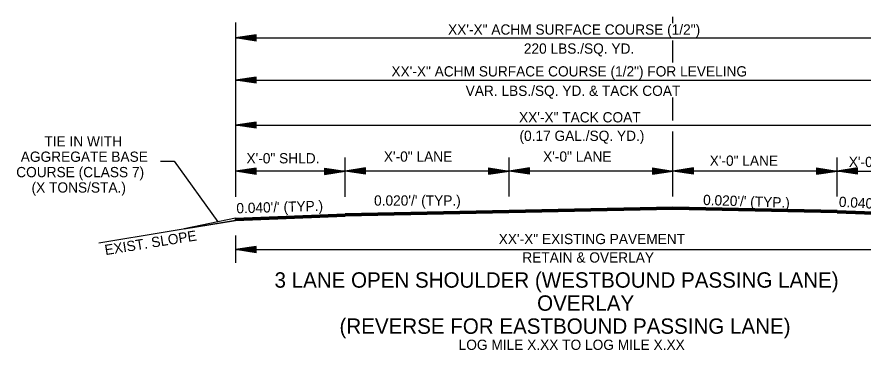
# Model space of a CAD drawing. Extents: x 544199 to 1930787, y -1968972 to 596640.
# Drawn here: x 551476 to 552096, y -1960786 to -1960542 of the extents above; entities that cross this region are included whole.
import ezdxf

# ---------------------------------------------------------------- set-up
doc = ezdxf.new("R2010")
doc.units = 0
doc.layers.add('R_Draft', color=7, linetype='Continuous')

msp = doc.modelspace()

# ---------------------------------------------------------------- linework, layer by layer
at = {"layer": 'R_Draft'}
for p, q in [((551636.39, -1960546.59), (551636.39, -1960674.01)), ((551956.58, -1960547.07), (551956.58, -1960542.46)), ((551651.39, -1960555.6), (551636.39, -1960557.85)), ((551636.39, -1960557.85), (552156.84, -1960557.85)), ((551651.39, -1960560.1), (551636.39, -1960557.85)), ((551651.39, -1960555.97), (551638.89, -1960557.85)), ((551651.39, -1960559.72), (551638.89, -1960557.85)), ((551651.39, -1960556.36), (551641.47, -1960557.85)), ((551651.39, -1960559.34), (551641.47, -1960557.85)), ((551651.39, -1960556.73), (551643.97, -1960557.85)), ((551651.39, -1960558.97), (551643.97, -1960557.85)), ((551651.39, -1960557.11), (551646.51, -1960557.85)), ((551651.39, -1960558.58), (551646.51, -1960557.85)), ((551651.39, -1960557.5), (551649.02, -1960557.85)), ((551651.39, -1960558.2), (551649.02, -1960557.85)), ((551651.39, -1960560.1), (551651.39, -1960555.6)), ((551956.58, -1960575.74), (551956.58, -1960559.67)), ((551651.39, -1960586.47), (551636.39, -1960588.72)), ((551636.39, -1960588.72), (552156.84, -1960588.72)), ((551651.39, -1960590.97), (551636.39, -1960588.72)), ((551651.39, -1960586.84), (551638.89, -1960588.72)), ((551651.39, -1960590.59), (551638.89, -1960588.72)), ((551651.39, -1960587.23), (551641.47, -1960588.72)), ((551651.39, -1960590.21), (551641.47, -1960588.72)), ((551651.39, -1960587.6), (551643.97, -1960588.72)), ((551651.39, -1960589.84), (551643.97, -1960588.72)), ((551651.39, -1960587.98), (551646.51, -1960588.72)), ((551651.39, -1960589.45), (551646.51, -1960588.72)), ((551651.39, -1960588.37), (551649.02, -1960588.72)), ((551651.39, -1960589.07), (551649.02, -1960588.72)), ((551651.39, -1960590.97), (551651.39, -1960586.47)), ((551956.58, -1960618.29), (551956.58, -1960601.42)), ((551651.39, -1960619.4), (551636.39, -1960621.65)), ((551651.39, -1960619.77), (551638.89, -1960621.65)), ((551651.39, -1960620.16), (551641.47, -1960621.65)), ((551651.39, -1960620.53), (551643.97, -1960621.65)), ((551651.39, -1960620.91), (551646.51, -1960621.65)), ((551651.39, -1960621.3), (551649.02, -1960621.65)), ((551651.39, -1960623.9), (551651.39, -1960619.4)), ((551636.39, -1960621.65), (552156.84, -1960621.65)), ((551651.39, -1960623.9), (551636.39, -1960621.65)), ((551651.39, -1960623.52), (551638.89, -1960621.65)), ((551651.39, -1960623.14), (551641.47, -1960621.65)), ((551651.39, -1960622.77), (551643.97, -1960621.65)), ((551651.39, -1960622.38), (551646.51, -1960621.65)), ((551651.39, -1960622), (551649.02, -1960621.65)), ((551956.58, -1960673.84), (551956.58, -1960626.29)), ((551716.65, -1960673.84), (551716.65, -1960645.29)), ((551716.65, -1960674.01), (551716.65, -1960645.29)), ((551836.65, -1960673.84), (551836.65, -1960645.29)), ((552076.84, -1960673.84), (552076.84, -1960645.29)), ((551651.39, -1960653.11), (551636.39, -1960655.36)), ((551716.65, -1960655.36), (551636.39, -1960655.36)), ((551651.39, -1960657.61), (551636.39, -1960655.36)), ((551651.39, -1960653.48), (551638.89, -1960655.36)), ((551651.39, -1960657.23), (551638.89, -1960655.36)), ((551651.39, -1960653.86), (551641.47, -1960655.36)), ((551651.39, -1960656.85), (551641.47, -1960655.36)), ((551651.39, -1960654.24), (551643.97, -1960655.36)), ((551651.39, -1960656.47), (551643.97, -1960655.36)), ((551651.39, -1960654.62), (551646.51, -1960655.36)), ((551651.39, -1960656.08), (551646.51, -1960655.36)), ((551651.39, -1960655), (551649.02, -1960655.36)), ((551651.39, -1960655.71), (551649.02, -1960655.36)), ((551651.39, -1960657.61), (551651.39, -1960653.11)), ((551701.65, -1960653.11), (551716.65, -1960655.36)), ((551701.65, -1960653.11), (551701.65, -1960657.61)), ((551701.65, -1960653.48), (551714.14, -1960655.36)), ((551701.65, -1960653.86), (551711.56, -1960655.36)), ((551701.65, -1960654.24), (551709.07, -1960655.36)), ((551701.65, -1960654.63), (551706.52, -1960655.36)), ((551701.65, -1960655), (551704.02, -1960655.36)), ((551701.65, -1960657.61), (551716.65, -1960655.36)), ((551701.65, -1960656.09), (551706.52, -1960655.36)), ((551701.65, -1960656.85), (551711.56, -1960655.36)), ((551701.65, -1960657.23), (551714.14, -1960655.36)), ((551701.65, -1960656.47), (551709.07, -1960655.36)), ((551701.65, -1960655.71), (551704.02, -1960655.36)), ((551731.65, -1960652.94), (551716.65, -1960655.19)), ((551836.65, -1960655.19), (551716.65, -1960655.19)), ((551731.65, -1960657.44), (551716.65, -1960655.19)), ((551731.65, -1960653.31), (551719.15, -1960655.19)), ((551731.65, -1960657.06), (551719.15, -1960655.19)), ((551731.65, -1960653.69), (551721.73, -1960655.19)), ((551731.65, -1960656.68), (551721.73, -1960655.19)), ((551731.65, -1960654.07), (551724.23, -1960655.19)), ((551731.65, -1960656.3), (551724.23, -1960655.19)), ((551731.65, -1960654.45), (551726.77, -1960655.19)), ((551731.65, -1960655.91), (551726.77, -1960655.19)), ((551731.65, -1960654.83), (551729.28, -1960655.19)), ((551731.65, -1960655.54), (551729.28, -1960655.19)), ((551731.65, -1960657.44), (551731.65, -1960652.94)), ((551821.65, -1960652.94), (551836.65, -1960655.19)), ((551821.65, -1960652.94), (551821.65, -1960657.44)), ((551821.65, -1960653.31), (551834.14, -1960655.19)), ((551821.65, -1960653.69), (551831.56, -1960655.19)), ((551821.65, -1960654.07), (551829.07, -1960655.19)), ((551821.65, -1960654.46), (551826.52, -1960655.19)), ((551821.65, -1960654.83), (551824.02, -1960655.19)), ((551821.65, -1960657.44), (551836.65, -1960655.19)), ((551821.65, -1960655.92), (551826.52, -1960655.19)), ((551821.65, -1960656.68), (551831.56, -1960655.19)), ((551821.65, -1960657.06), (551834.14, -1960655.19)), ((551821.65, -1960656.3), (551829.07, -1960655.19)), ((551821.65, -1960655.54), (551824.02, -1960655.19)), ((551851.65, -1960652.94), (551836.65, -1960655.19)), ((551956.58, -1960655.19), (551836.65, -1960655.19)), ((551851.65, -1960657.44), (551836.65, -1960655.19)), ((551851.65, -1960653.31), (551839.15, -1960655.19)), ((551851.65, -1960657.06), (551839.15, -1960655.19)), ((551851.65, -1960653.69), (551841.73, -1960655.19)), ((551851.65, -1960656.68), (551841.73, -1960655.19)), ((551851.65, -1960654.07), (551844.23, -1960655.19)), ((551851.65, -1960656.3), (551844.23, -1960655.19)), ((551851.65, -1960654.45), (551846.77, -1960655.19)), ((551851.65, -1960655.91), (551846.77, -1960655.19)), ((551851.65, -1960654.83), (551849.28, -1960655.19)), ((551851.65, -1960655.54), (551849.28, -1960655.19)), ((551851.65, -1960657.44), (551851.65, -1960652.94)), ((551941.58, -1960652.94), (551956.58, -1960655.19)), ((551941.58, -1960652.94), (551941.58, -1960657.44)), ((551941.58, -1960653.31), (551954.07, -1960655.19)), ((551941.58, -1960653.69), (551951.49, -1960655.19)), ((551941.58, -1960654.07), (551948.99, -1960655.19)), ((551941.58, -1960654.46), (551946.45, -1960655.19)), ((551941.58, -1960654.83), (551943.95, -1960655.19)), ((551941.58, -1960657.44), (551956.58, -1960655.19)), ((551941.58, -1960655.92), (551946.45, -1960655.19)), ((551941.58, -1960656.68), (551951.49, -1960655.19)), ((551941.58, -1960657.06), (551954.07, -1960655.19)), ((551941.58, -1960656.3), (551948.99, -1960655.19)), ((551941.58, -1960655.54), (551943.95, -1960655.19)), ((551971.58, -1960652.94), (551956.58, -1960655.19)), ((552076.84, -1960655.19), (551956.58, -1960655.19)), ((551971.58, -1960657.44), (551956.58, -1960655.19)), ((551971.58, -1960653.31), (551959.08, -1960655.19)), ((551971.58, -1960657.06), (551959.08, -1960655.19)), ((551971.58, -1960653.69), (551961.66, -1960655.19)), ((551971.58, -1960656.68), (551961.66, -1960655.19)), ((551971.58, -1960654.07), (551964.16, -1960655.19)), ((551971.58, -1960656.3), (551964.16, -1960655.19)), ((551971.58, -1960654.45), (551966.7, -1960655.19)), ((551971.58, -1960655.91), (551966.7, -1960655.19)), ((551971.58, -1960654.83), (551969.21, -1960655.19)), ((551971.58, -1960655.54), (551969.21, -1960655.19)), ((551971.58, -1960657.44), (551971.58, -1960652.94)), ((552061.84, -1960652.94), (552076.84, -1960655.19)), ((552061.84, -1960652.94), (552061.84, -1960657.44)), ((552061.84, -1960653.31), (552074.33, -1960655.19)), ((552061.84, -1960653.69), (552071.75, -1960655.19)), ((552061.84, -1960654.07), (552069.25, -1960655.19)), ((552061.84, -1960654.46), (552066.71, -1960655.19)), ((552061.84, -1960654.83), (552064.21, -1960655.19)), ((552061.84, -1960657.44), (552076.84, -1960655.19)), ((552061.84, -1960655.92), (552066.71, -1960655.19)), ((552061.84, -1960656.68), (552071.75, -1960655.19)), ((552061.84, -1960657.06), (552074.33, -1960655.19)), ((552061.84, -1960656.3), (552069.25, -1960655.19)), ((552061.84, -1960655.54), (552064.21, -1960655.19)), ((552091.84, -1960652.94), (552076.84, -1960655.19)), ((552076.84, -1960655.19), (552156.84, -1960655.19)), ((552091.84, -1960657.44), (552076.84, -1960655.19)), ((552091.84, -1960653.31), (552079.34, -1960655.19)), ((552091.84, -1960657.06), (552079.34, -1960655.19)), ((552091.84, -1960653.69), (552081.92, -1960655.19)), ((552091.84, -1960656.68), (552081.92, -1960655.19)), ((552091.84, -1960654.07), (552084.42, -1960655.19)), ((552091.84, -1960656.3), (552084.42, -1960655.19)), ((552091.84, -1960654.45), (552086.96, -1960655.19)), ((552091.84, -1960655.91), (552086.96, -1960655.19)), ((552091.84, -1960654.83), (552089.47, -1960655.19)), ((552091.84, -1960655.54), (552089.47, -1960655.19)), ((552091.84, -1960657.44), (552091.84, -1960652.94)), ((551956.58, -1960681.59), (551716.65, -1960686.39)), ((551956.58, -1960681.89), (551716.65, -1960686.69)), ((551956.58, -1960682.19), (551716.66, -1960686.99)), ((551956.58, -1960682.49), (551716.67, -1960687.29)), ((551956.58, -1960682.79), (551716.67, -1960687.59)), ((551956.58, -1960683.09), (551716.68, -1960687.89)), ((551956.58, -1960683.29), (551716.68, -1960688.09)), ((552076.84, -1960684), (551956.58, -1960681.59)), ((552076.83, -1960684.3), (551956.58, -1960681.89)), ((552076.82, -1960684.6), (551956.58, -1960682.19)), ((552076.82, -1960684.9), (551956.58, -1960682.49)), ((552076.81, -1960685.2), (551956.58, -1960682.79)), ((552076.81, -1960685.5), (551956.58, -1960683.09)), ((552076.8, -1960685.7), (551956.58, -1960683.29)), ((551636.39, -1960689.6), (551716.65, -1960686.39)), ((551636.39, -1960689.9), (551716.66, -1960686.69)), ((551636.39, -1960690.2), (551716.67, -1960686.99)), ((551636.39, -1960690.5), (551716.68, -1960687.29)), ((551636.39, -1960690.8), (551716.7, -1960687.59)), ((551636.39, -1960691.1), (551716.71, -1960687.89)), ((551636.39, -1960691.3), (551716.72, -1960688.09)), ((552076.77, -1960685.7), (552157.11, -1960688.91)), ((552076.78, -1960685.5), (552157.1, -1960688.71)), ((552076.79, -1960685.2), (552157.1, -1960688.41)), ((552076.8, -1960684.9), (552157.1, -1960688.11)), ((552076.81, -1960684.6), (552157.1, -1960687.81)), ((552076.82, -1960684.3), (552157.1, -1960687.51)), ((552076.84, -1960684), (552157.1, -1960687.21)), ((551636.39, -1960691.3), (551536.32, -1960707.98)), ((551636.39, -1960689.6), (551598.89, -1960697.55)), ((551598.89, -1960697.55), (551636.39, -1960691.3)), ((551636.39, -1960691.3), (551636.39, -1960689.6)), ((551636.39, -1960689.6), (551636.39, -1960691.3)), ((551636.39, -1960691.3), (551636.39, -1960691.3)), ((551636.39, -1960702.4), (551636.39, -1960722.4)), ((551651.39, -1960710.4), (551636.39, -1960712.65)), ((551636.39, -1960712.65), (552156.84, -1960712.65)), ((551651.39, -1960714.9), (551636.39, -1960712.65)), ((551651.39, -1960710.78), (551638.89, -1960712.65)), ((551651.39, -1960714.53), (551638.89, -1960712.65)), ((551651.39, -1960711.16), (551641.47, -1960712.65)), ((551651.39, -1960714.14), (551641.47, -1960712.65)), ((551651.39, -1960711.53), (551643.97, -1960712.65)), ((551651.39, -1960713.77), (551643.97, -1960712.65)), ((551651.39, -1960711.92), (551646.51, -1960712.65)), ((551651.39, -1960713.38), (551646.51, -1960712.65)), ((551651.39, -1960712.3), (551649.02, -1960712.65)), ((551651.39, -1960713), (551649.02, -1960712.65)), ((551651.39, -1960714.9), (551651.39, -1960710.4))]:
    msp.add_line(p, q, dxfattribs=at)
msp.add_lwpolyline([(551581.54, -1960647.91), (551591.54, -1960647.91), (551623.45, -1960692.34)], dxfattribs=at)

# ---------------------------------------------------------------- texts
for s, height, p in [('XX\'-X" ACHM SURFACE COURSE (1/2")', 7.5, (551791.99, -1960555.41)), ('220 LBS./SQ. YD. ', 7.5, (551847.47, -1960569.35)), ('XX\'-X" ACHM SURFACE COURSE (1/2") FOR LEVELING', 7.5, (551750.52, -1960586.01)), ('VAR. LBS./SQ. YD. & TACK COAT', 7.5, (551804.87, -1960600.22)), ('XX\'-X" TACK COAT', 7.5, (551843.93, -1960619.61)), ('(0.17 GAL./SQ. YD.)', 7.5, (551844.29, -1960633.15)), ('TIE IN WITH ', 7.5, (551496.46, -1960637.19)), ('AGGREGATE BASE', 7.5, (551479.16, -1960648.44)), ('X\'-0" SHLD.', 7.5, (551644.42, -1960649.58)), ('X\'-0" LANE', 7.5, (551744.99, -1960648.32)), ('X\'-0" LANE', 7.5, (551861.58, -1960648.32)), ('X\'-0" LANE', 7.5, (551983.53, -1960651.35)), ('X\'-0" SHLD.', 7.5, (552085.36, -1960652.27)), ('COURSE (CLASS 7)', 7.5, (551475.85, -1960659.69)), ('(X TONS/STA.)', 7.5, (551487.07, -1960670.94)), ("0.020'/' (TYP.)", 7.5, (551737.82, -1960680.48)), ('XX\'-X" EXISTING PAVEMENT', 7.5, (551829.06, -1960708.63)), ('RETAIN & OVERLAY', 7.5, (551846.35, -1960722.14)), ('3 LANE OPEN SHOULDER (WESTBOUND PASSING LANE) ', 11.25, (551664.96, -1960740.5)), ('OVERLAY', 11.25, (551857.19, -1960757.37)), ('(REVERSE FOR EASTBOUND PASSING LANE)', 11.25, (551712.53, -1960774.25)), ('LOG MILE X.XX TO LOG MILE X.XX', 7.5, (551799.74, -1960786.02))]:
    msp.add_text(s, height=height, dxfattribs=at).set_placement(p)
for s, rotation, p in [("0.040'/' (TYP.)", 1.70227, (551637.13, -1960686.16)), ("0.020'/' (TYP.)", 358.06067, (551978.6, -1960679.97)), ("0.040'/' (TYP.)", 356.93347, (552077.93, -1960681.35)), ('EXIST. SLOPE', 9.15344, (551541.23, -1960716.73))]:
    msp.add_text(s, height=7.5, rotation=rotation, dxfattribs=at).set_placement(p)

doc.saveas('drawing.dxf')
